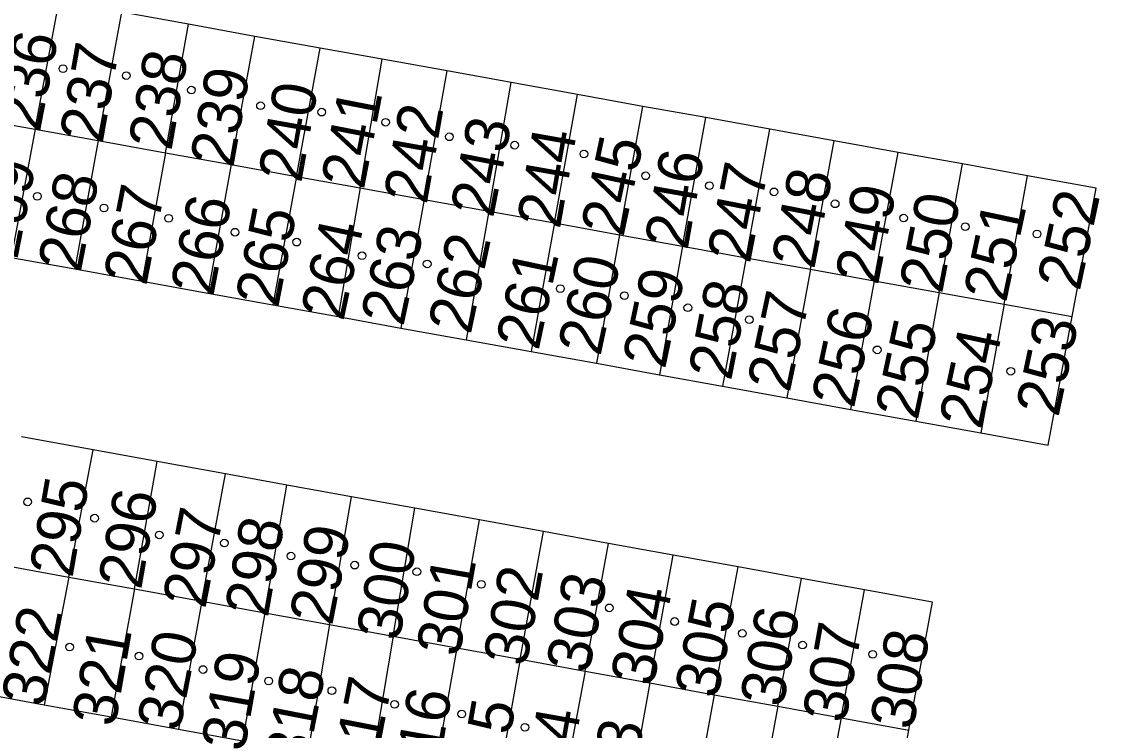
# Model space of a CAD drawing. Extents: x -555757 to -553364, y -1100723 to -1096439.
# Drawn here: x -553880.15 to -553831.19, y -1100665.96 to -1100633.79 of the extents above; entities that cross this region are included whole.
import ezdxf

# ---------------------------------------------------------------- set-up
doc = ezdxf.new("R2010")
doc.units = 0
for name, color, linetype in [('BUDOVY', 7, 'Continuous'), ('C$SLO$PARCELY', 7, 'Continuous'), ('HRANICE$PARCELY', 7, 'Continuous'), ('SLOUPY', 7, 'Continuous')]:
    doc.layers.add(name, color=color, linetype=linetype)

# ---------------------------------------------------------------- blocks, each defined once
blk = doc.blocks.new('4$02')
at = {"layer": 'SLOUPY'}
blk.add_circle((0, 0), 0.175, dxfattribs=at)

msp = doc.modelspace()

# ---------------------------------------------------------------- linework, layer by layer
at = {"layer": 'HRANICE$PARCELY'}
for p, q in [((-553879.53, -1100638.67), (-553878.44, -1100632.85)), ((-553876.67, -1100639.19), (-553875.6, -1100633.37)), ((-553872.57, -1100633.91), (-553875.6, -1100633.37)), ((-553873.62, -1100639.74), (-553872.57, -1100633.91)), ((-553869.56, -1100634.46), (-553872.57, -1100633.91)), ((-553870.63, -1100640.28), (-553869.56, -1100634.46)), ((-553866.59, -1100634.99), (-553869.56, -1100634.46)), ((-553867.67, -1100640.82), (-553866.59, -1100634.99)), ((-553863.78, -1100635.5), (-553866.59, -1100634.99)), ((-553864.78, -1100641.34), (-553863.78, -1100635.5)), ((-553860.82, -1100636.03), (-553863.78, -1100635.5)), ((-553861.87, -1100641.86), (-553860.82, -1100636.03)), ((-553857.91, -1100636.56), (-553860.82, -1100636.03)), ((-553858.93, -1100642.4), (-553857.91, -1100636.56)), ((-553854.9, -1100637.1), (-553857.91, -1100636.56)), ((-553855.95, -1100642.93), (-553854.9, -1100637.1)), ((-553851.94, -1100637.64), (-553854.9, -1100637.1)), ((-553852.99, -1100643.47), (-553851.94, -1100637.64)), ((-553849.07, -1100638.15), (-553851.94, -1100637.64)), ((-553882.41, -1100638.16), (-553879.53, -1100638.67)), ((-553850.13, -1100643.99), (-553849.07, -1100638.15)), ((-553846.16, -1100638.68), (-553849.07, -1100638.15)), ((-553879.53, -1100638.67), (-553880.63, -1100644.5)), ((-553879.53, -1100638.67), (-553876.67, -1100639.19)), ((-553847.24, -1100644.51), (-553846.16, -1100638.68)), ((-553843.25, -1100639.2), (-553846.16, -1100638.68)), ((-553876.67, -1100639.19), (-553877.74, -1100645.02)), ((-553876.67, -1100639.19), (-553873.62, -1100639.74)), ((-553844.32, -1100645.03), (-553843.25, -1100639.2)), ((-553840.34, -1100639.73), (-553843.25, -1100639.2)), ((-553873.62, -1100639.74), (-553874.68, -1100645.57)), ((-553873.62, -1100639.74), (-553870.63, -1100640.28)), ((-553841.42, -1100645.56), (-553840.34, -1100639.73)), ((-553837.42, -1100640.25), (-553840.34, -1100639.73)), ((-553870.63, -1100640.28), (-553871.7, -1100646.11)), ((-553870.63, -1100640.28), (-553867.67, -1100640.82)), ((-553838.48, -1100646.09), (-553837.42, -1100640.25)), ((-553834.46, -1100640.79), (-553837.42, -1100640.25)), ((-553867.67, -1100640.82), (-553868.74, -1100646.64)), ((-553867.67, -1100640.82), (-553864.78, -1100641.34)), ((-553835.52, -1100646.62), (-553834.46, -1100640.79)), ((-553864.78, -1100641.34), (-553865.78, -1100647.18)), ((-553864.78, -1100641.34), (-553861.87, -1100641.86)), ((-553861.87, -1100641.86), (-553862.92, -1100647.7)), ((-553861.87, -1100641.86), (-553858.93, -1100642.4)), ((-553858.93, -1100642.4), (-553859.96, -1100648.23)), ((-553858.93, -1100642.4), (-553855.95, -1100642.93)), ((-553855.95, -1100642.93), (-553857, -1100648.77)), ((-553855.95, -1100642.93), (-553852.99, -1100643.47)), ((-553852.99, -1100643.47), (-553854.04, -1100649.3)), ((-553852.99, -1100643.47), (-553850.13, -1100643.99)), ((-553850.13, -1100643.99), (-553851.18, -1100649.82)), ((-553850.13, -1100643.99), (-553847.24, -1100644.51)), ((-553880.63, -1100644.5), (-553877.74, -1100645.02)), ((-553847.24, -1100644.51), (-553848.32, -1100650.34)), ((-553847.24, -1100644.51), (-553844.32, -1100645.03)), ((-553877.74, -1100645.02), (-553874.68, -1100645.57)), ((-553844.32, -1100645.03), (-553845.39, -1100650.87)), ((-553844.32, -1100645.03), (-553841.42, -1100645.56)), ((-553874.68, -1100645.57), (-553871.7, -1100646.11)), ((-553841.42, -1100645.56), (-553842.5, -1100651.39)), ((-553841.42, -1100645.56), (-553838.48, -1100646.09)), ((-553871.7, -1100646.11), (-553868.74, -1100646.64)), ((-553838.48, -1100646.09), (-553839.54, -1100651.92)), ((-553838.48, -1100646.09), (-553835.52, -1100646.62)), ((-553868.74, -1100646.64), (-553865.78, -1100647.18)), ((-553835.52, -1100646.62), (-553836.58, -1100652.46)), ((-553835.52, -1100646.62), (-553832.44, -1100647.18)), ((-553865.78, -1100647.18), (-553862.92, -1100647.7)), ((-553862.92, -1100647.7), (-553859.96, -1100648.23)), ((-553859.96, -1100648.23), (-553857, -1100648.77)), ((-553857, -1100648.77), (-553854.04, -1100649.3)), ((-553854.04, -1100649.3), (-553851.18, -1100649.82)), ((-553851.18, -1100649.82), (-553848.32, -1100650.34)), ((-553848.32, -1100650.34), (-553845.39, -1100650.87)), ((-553845.39, -1100650.87), (-553842.5, -1100651.39)), ((-553842.5, -1100651.39), (-553839.54, -1100651.92)), ((-553839.54, -1100651.92), (-553836.58, -1100652.46)), ((-553876.9, -1100653.23), (-553880.16, -1100652.64)), ((-553878.01, -1100659), (-553876.9, -1100653.23)), ((-553873.99, -1100653.76), (-553876.9, -1100653.23)), ((-553875.03, -1100659.54), (-553873.99, -1100653.76)), ((-553870.89, -1100654.32), (-553873.99, -1100653.76)), ((-553871.96, -1100660.1), (-553870.89, -1100654.32)), ((-553868.11, -1100654.83), (-553870.89, -1100654.32)), ((-553869.11, -1100660.62), (-553868.11, -1100654.83)), ((-553865.17, -1100655.36), (-553868.11, -1100654.83)), ((-553866.16, -1100661.16), (-553865.17, -1100655.36)), ((-553862.29, -1100655.88), (-553865.17, -1100655.36)), ((-553863.28, -1100661.68), (-553862.29, -1100655.88)), ((-553859.36, -1100656.41), (-553862.29, -1100655.88)), ((-553860.38, -1100662.21), (-553859.36, -1100656.41)), ((-553856.45, -1100656.94), (-553859.36, -1100656.41)), ((-553857.5, -1100662.73), (-553856.45, -1100656.94)), ((-553853.49, -1100657.48), (-553856.45, -1100656.94)), ((-553854.56, -1100663.27), (-553853.49, -1100657.48)), ((-553850.56, -1100658.01), (-553853.49, -1100657.48)), ((-553851.62, -1100663.8), (-553850.56, -1100658.01)), ((-553847.6, -1100658.54), (-553850.56, -1100658.01)), ((-553881.13, -1100658.43), (-553878.01, -1100659)), ((-553848.69, -1100664.34), (-553847.6, -1100658.54)), ((-553844.73, -1100659.06), (-553847.6, -1100658.54)), ((-553878.01, -1100659), (-553879.13, -1100664.8)), ((-553878.01, -1100659), (-553875.03, -1100659.54)), ((-553845.8, -1100664.86), (-553844.73, -1100659.06)), ((-553841.86, -1100659.58), (-553844.73, -1100659.06)), ((-553875.03, -1100659.54), (-553876.08, -1100665.35)), ((-553875.03, -1100659.54), (-553871.96, -1100660.1)), ((-553842.93, -1100665.39), (-553841.86, -1100659.58)), ((-553871.96, -1100660.1), (-553873.03, -1100665.91)), ((-553871.96, -1100660.1), (-553869.11, -1100660.62)), ((-553869.11, -1100660.62), (-553870.12, -1100666.44)), ((-553869.11, -1100660.62), (-553866.16, -1100661.16)), ((-553866.16, -1100661.16), (-553867.15, -1100666.98)), ((-553866.16, -1100661.16), (-553863.28, -1100661.68)), ((-553863.28, -1100661.68), (-553864.26, -1100667.5)), ((-553863.28, -1100661.68), (-553860.38, -1100662.21)), ((-553860.38, -1100662.21), (-553861.41, -1100668.02)), ((-553860.38, -1100662.21), (-553857.5, -1100662.73)), ((-553857.5, -1100662.73), (-553858.55, -1100668.54)), ((-553857.5, -1100662.73), (-553854.56, -1100663.27)), ((-553854.56, -1100663.27), (-553855.63, -1100669.08)), ((-553854.56, -1100663.27), (-553851.62, -1100663.8)), ((-553851.62, -1100663.8), (-553852.67, -1100669.61)), ((-553851.62, -1100663.8), (-553848.69, -1100664.34)), ((-553882.12, -1100664.25), (-553879.13, -1100664.8)), ((-553848.69, -1100664.34), (-553849.77, -1100670.14)), ((-553848.69, -1100664.34), (-553845.8, -1100664.86)), ((-553879.13, -1100664.8), (-553876.08, -1100665.35)), ((-553845.8, -1100664.86), (-553846.87, -1100670.67)), ((-553845.8, -1100664.86), (-553842.93, -1100665.39)), ((-553876.08, -1100665.35), (-553873.03, -1100665.91)), ((-553842.93, -1100665.39), (-553844.01, -1100671.19)), ((-553842.93, -1100665.39), (-553839.85, -1100665.95)), ((-553873.03, -1100665.91), (-553870.12, -1100666.44))]:
    msp.add_line(p, q, dxfattribs=at)
for points in [[(-553832.44, -1100647.18), (-553831.35, -1100641.35), (-553834.46, -1100640.79)], [(-553836.58, -1100652.46), (-553833.53, -1100653.01), (-553832.44, -1100647.18)], [(-553839.85, -1100665.95), (-553838.78, -1100660.14), (-553841.86, -1100659.58)], [(-553844.01, -1100671.19), (-553840.93, -1100671.75), (-553839.85, -1100665.95)]]:
    msp.add_lwpolyline(points, dxfattribs=at)

# ---------------------------------------------------------------- block references
at = {"layer": 'BUDOVY'}
for p in [(-553878.27, -1100635.93), (-553875.4, -1100636.24), (-553872.44, -1100636.9), (-553869.3, -1100637.61), (-553866.52, -1100637.9), (-553863.62, -1100638.36), (-553860.72, -1100639.02), (-553857.76, -1100639.4), (-553854.61, -1100639.8), (-553851.81, -1100640.79), (-553848.91, -1100641.24), (-553879.44, -1100641.72), (-553845.98, -1100641.52), (-553876.41, -1100642.25), (-553843.2, -1100642.06), (-553873.47, -1100642.72), (-553840.09, -1100642.71), (-553837.29, -1100643.1), (-553870.46, -1100643.35), (-553834.03, -1100643.43), (-553867.66, -1100643.8), (-553864.69, -1100644.42), (-553861.73, -1100644.79), (-553855.68, -1100645.91), (-553852.77, -1100646.23), (-553849.89, -1100646.78), (-553847.1, -1100647.32), (-553841.29, -1100648.69), (-553835.22, -1100649.66), (-553879.88, -1100655.59), (-553876.84, -1100656.33), (-553873.9, -1100657.09), (-553870.94, -1100657.46), (-553867.92, -1100658.05), (-553865.02, -1100658.46), (-553862.2, -1100658.76), (-553859.27, -1100659.33), (-553853.46, -1100660.4), (-553850.49, -1100661.02), (-553847.42, -1100661.56), (-553877.97, -1100662.18), (-553844.68, -1100662.09), (-553874.82, -1100662.59), (-553841.49, -1100662.51), (-553871.91, -1100663.2), (-553868.93, -1100663.72), (-553866.06, -1100664.16), (-553863.21, -1100664.78), (-553860.16, -1100665.22), (-553857.29, -1100665.82)]:
    msp.add_blockref('4$02', p, dxfattribs=at)

# ---------------------------------------------------------------- texts
at = {"layer": 'C$SLO$PARCELY'}
for s, rotation, p in [('236', 79, (-553879.326, -1100638.84)), ('237', 80, (-553876.479, -1100639.366)), ('238', 80, (-553873.353, -1100639.693)), ('239', 80, (-553870.546, -1100640.468)), ('240', 80, (-553867.454, -1100641.153)), ('241', 79, (-553864.612, -1100641.457)), ('242', 80, (-553861.757, -1100642.128)), ('243', 79, (-553858.736, -1100642.74)), ('244', 80, (-553855.707, -1100643.244)), ('245', 78, (-553852.822, -1100643.609)), ('269', 79, (-553880.349, -1100644.626)), ('246', 80, (-553849.907, -1100644.204)), ('247', 79, (-553847.073, -1100644.812)), ('248', 79, (-553844.155, -1100645.07)), ('268', 79, (-553877.475, -1100645.23)), ('267', 79, (-553874.493, -1100645.822)), ('249', 79, (-553841.259, -1100645.796)), ('250', 79, (-553838.348, -1100646.18)), ('252', 78, (-553832.094, -1100646.065)), ('266', 79, (-553871.449, -1100646.286)), ('265', 79, (-553868.501, -1100646.807)), ('251', 78, (-553835.438, -1100646.582)), ('264', 78, (-553865.54, -1100647.427)), ('263', 78, (-553862.816, -1100647.662)), ('262', 78, (-553859.758, -1100648.031)), ('261', 78, (-553856.675, -1100648.758)), ('260', 78, (-553853.865, -1100649.017)), ('259', 78, (-553850.932, -1100649.602)), ('258', 79, (-553847.929, -1100650.135)), ('257', 78, (-553845.268, -1100650.668)), ('256', 78, (-553842.352, -1100651.382)), ('255', 78, (-553839.455, -1100651.923)), ('253', 78, (-553833.064, -1100651.785)), ('254', 78, (-553836.552, -1100652.352)), ('295', 80, (-553877.849, -1100659.076)), ('296', 80, (-553874.727, -1100659.614)), ('297', 79, (-553871.813, -1100660.482)), ('298', 80, (-553868.974, -1100660.878)), ('299', 79, (-553866.049, -1100661.246)), ('300', 80, (-553862.996, -1100661.95)), ('301', 80, (-553860.272, -1100662.662)), ('302', 80, (-553857.23, -1100663.104)), ('303', 79, (-553854.389, -1100663.426)), ('304', 79, (-553851.461, -1100664.011)), ('305', 79, (-553848.544, -1100664.564)), ('322', 79, (-553879.134, -1100664.951)), ('306', 80, (-553845.57, -1100664.96)), ('307', 80, (-553842.734, -1100665.678)), ('321', 80, (-553875.915, -1100665.846)), ('320', 79, (-553872.971, -1100666.056)), ('308', 80, (-553839.668, -1100665.986)), ('319', 80, (-553870.04, -1100666.973)), ('318', 79, (-553867.193, -1100667.668)), ('317', 79, (-553864.161, -1100668.16)), ('316', 80, (-553861.37, -1100668.643)), ('315', 80, (-553858.472, -1100669.145)), ('314', 80, (-553855.52, -1100669.533)), ('313', 80, (-553852.648, -1100670.056))]:
    msp.add_text(s, height=2, rotation=rotation, dxfattribs=at).set_placement(p)

doc.saveas('drawing.dxf')
